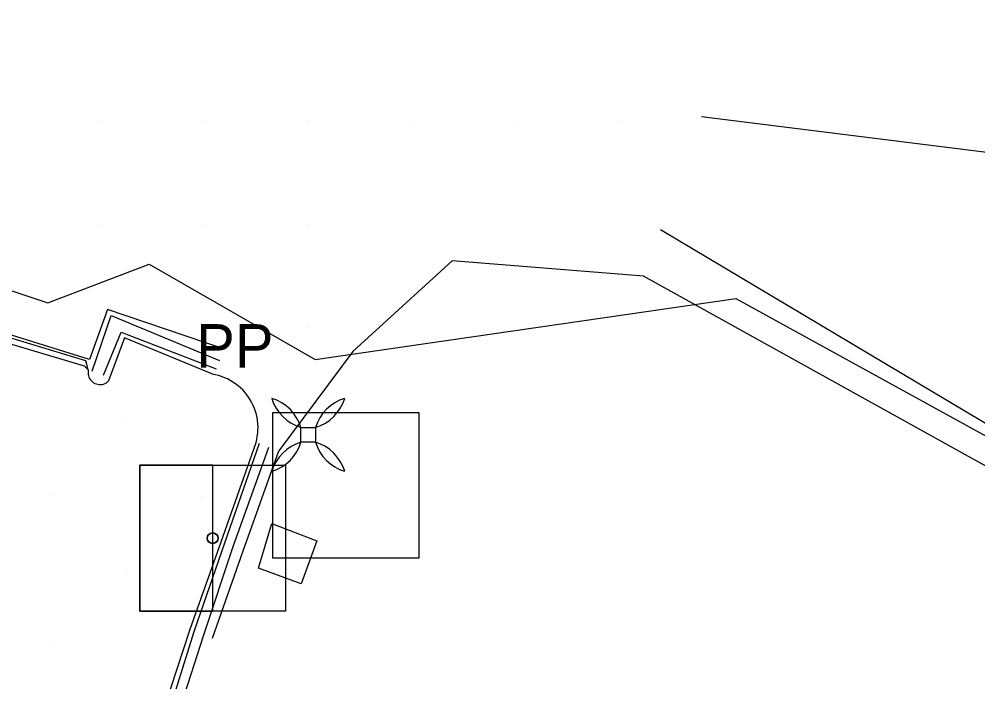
# Model space of a CAD drawing. Extents: x 1602514 to 1609837, y 863887 to 871157.
# Drawn here: x 1604009.5 to 1604147.6, y 867540.9 to 867636.3 of the extents above; entities that cross this region are included whole.
import ezdxf

# ---------------------------------------------------------------- set-up
doc = ezdxf.new("R2010")
doc.units = 0
for name, color, linetype in [('Photo-Anchor', 7, 'Continuous'), ('Survey-Buildings', 7, 'Continuous'), ('Survey-Curbs', 7, 'Continuous'), ('Survey-Edge of pavement', 7, 'Continuous'), ('Survey-Entrances', 7, 'Continuous'), ('Survey-Ridge Lines', 7, 'Continuous'), ('Survey-Spot dirt', 7, 'Continuous'), ('Survey-Vegetation trees', 7, 'Continuous'), ('Survey-Walls', 7, 'Continuous'), ('Utility-Pole', 7, 'Continuous')]:
    doc.layers.add(name, color=color, linetype=linetype)

msp = doc.modelspace()

# ---------------------------------------------------------------- linework, layer by layer
at = {"layer": 'Photo-Anchor'}
msp.add_lwpolyline([(1604050.09, 867577.53), (1604052.19, 867577.53), (1604052.19, 867575.43), (1604050.09, 867575.43)], close=True, dxfattribs=at)
msp.add_lwpolyline([(1604050.09, 867577.53), (1604052.19, 867577.53), (1604052.19, 867575.43), (1604050.09, 867575.43)], close=True, dxfattribs=at)
for centre, radius, start, end in [((1604044.09, 867575.72), 6.27, 16.7236, 73.2821), ((1604051.91, 867583.55), 6.29, 196.8106, 253.1951), ((1604044.09, 867575.72), 6.27, 16.7236, 73.2821), ((1604051.91, 867583.55), 6.29, 196.8106, 253.1951), ((1604058.19, 867575.72), 6.27, 106.7179, 163.2764), ((1604050.37, 867583.55), 6.29, 286.8049, 343.1894), ((1604058.19, 867575.72), 6.27, 106.7179, 163.2764), ((1604050.37, 867583.55), 6.29, 286.8049, 343.1894), ((1604044.09, 867577.23), 6.27, 286.7179, 343.2764), ((1604051.91, 867569.41), 6.29, 106.8049, 163.1894), ((1604044.09, 867577.23), 6.27, 286.7179, 343.2764), ((1604051.91, 867569.41), 6.29, 106.8049, 163.1894), ((1604058.19, 867577.23), 6.27, 196.7236, 253.2821), ((1604050.37, 867569.41), 6.29, 16.8106, 73.1951), ((1604058.19, 867577.23), 6.27, 196.7236, 253.2821), ((1604050.37, 867569.41), 6.29, 16.8106, 73.1951)]:
    msp.add_arc(centre, radius, start, end, dxfattribs=at)
at = {"layer": 'Survey-Buildings'}
msp.add_lwpolyline([(1604043.98, 867557.3), (1604045.89, 867563.73), (1604052.37, 867561.2), (1604050.11, 867555.03)], close=True, dxfattribs=at)
msp.add_lwpolyline([(1604043.98, 867557.3), (1604045.89, 867563.73), (1604052.37, 867561.2), (1604050.11, 867555.03)], close=True, dxfattribs=at)
at = {"layer": 'Survey-Curbs'}
for points in [[(1604019.47, 867585.84), (1604019.12, 867587.16), (1603987.37, 867596.76), (1603941.48, 867609.84), (1603941.32, 867609.45)], [(1604019.47, 867585.84), (1604019.12, 867587.16), (1603987.37, 867596.76), (1603941.48, 867609.84), (1603941.32, 867609.45)], [(1604019.47, 867585.84), (1604018.9, 867586.37), (1603987.01, 867595.85), (1603941.32, 867609.45)], [(1604019.47, 867585.84), (1604018.9, 867586.37), (1603987.01, 867595.85), (1603941.32, 867609.45)]]:
    msp.add_lwpolyline(points, dxfattribs=at)
at = {"layer": 'Survey-Edge of pavement'}
for points in [[(1604037.52, 867585.18), (1604024.7, 867590.46), (1604022.4, 867584.24)], [(1604037.52, 867585.18), (1604024.7, 867590.46), (1604022.4, 867584.24)], [(1604019.47, 867585.84), (1604019.43, 867585.63), (1604019.43, 867585.42), (1604019.44, 867585.21), (1604019.49, 867585), (1604019.56, 867584.79), (1604019.65, 867584.6), (1604019.77, 867584.42), (1604019.91, 867584.26), (1604020.07, 867584.12), (1604020.24, 867583.99), (1604020.43, 867583.89), (1604020.63, 867583.81), (1604020.83, 867583.76), (1604021.04, 867583.73), (1604021.26, 867583.73), (1604021.47, 867583.75), (1604021.68, 867583.8), (1604021.88, 867583.87), (1604022.07, 867583.97), (1604022.24, 867584.09), (1604022.4, 867584.24)], [(1604019.47, 867585.84), (1604019.43, 867585.63), (1604019.43, 867585.42), (1604019.44, 867585.21), (1604019.49, 867585), (1604019.56, 867584.79), (1604019.65, 867584.6), (1604019.77, 867584.42), (1604019.91, 867584.26), (1604020.07, 867584.12), (1604020.24, 867583.99), (1604020.43, 867583.89), (1604020.63, 867583.81), (1604020.83, 867583.76), (1604021.04, 867583.73), (1604021.26, 867583.73), (1604021.47, 867583.75), (1604021.68, 867583.8), (1604021.88, 867583.87), (1604022.07, 867583.97), (1604022.24, 867584.09), (1604022.4, 867584.24)], [(1604043.62, 867575.39), (1604043.73, 867575.83), (1604043.81, 867576.27), (1604043.87, 867576.72), (1604043.9, 867577.17), (1604043.91, 867577.63), (1604043.89, 867578.08), (1604043.84, 867578.53), (1604043.77, 867578.98), (1604043.67, 867579.42), (1604043.54, 867579.86), (1604043.4, 867580.28), (1604043.22, 867580.7), (1604043.02, 867581.11), (1604042.8, 867581.51), (1604042.56, 867581.89), (1604042.29, 867582.25), (1604042.01, 867582.61), (1604041.7, 867582.94), (1604041.38, 867583.26), (1604041.03, 867583.55), (1604040.68, 867583.83), (1604040.3, 867584.08), (1604039.91, 867584.32), (1604039.51, 867584.53), (1604039.1, 867584.71), (1604038.67, 867584.88), (1604038.24, 867585.01), (1604037.8, 867585.13), (1604037.52, 867585.18)], [(1604043.62, 867575.39), (1604043.73, 867575.83), (1604043.81, 867576.27), (1604043.87, 867576.72), (1604043.9, 867577.17), (1604043.91, 867577.63), (1604043.89, 867578.08), (1604043.84, 867578.53), (1604043.77, 867578.98), (1604043.67, 867579.42), (1604043.54, 867579.86), (1604043.4, 867580.28), (1604043.22, 867580.7), (1604043.02, 867581.11), (1604042.8, 867581.51), (1604042.56, 867581.89), (1604042.29, 867582.25), (1604042.01, 867582.61), (1604041.7, 867582.94), (1604041.38, 867583.26), (1604041.03, 867583.55), (1604040.68, 867583.83), (1604040.3, 867584.08), (1604039.91, 867584.32), (1604039.51, 867584.53), (1604039.1, 867584.71), (1604038.67, 867584.88), (1604038.24, 867585.01), (1604037.8, 867585.13), (1604037.52, 867585.18)], [(1604024.29, 867515.96), (1604024.24, 867517.26), (1604024.76, 867519.96), (1604034.14, 867548.5), (1604038.61, 867561.09), (1604043.62, 867575.39)], [(1604024.29, 867515.96), (1604024.24, 867517.26), (1604024.76, 867519.96), (1604034.14, 867548.5), (1604038.61, 867561.09), (1604043.62, 867575.39)]]:
    msp.add_lwpolyline(points, dxfattribs=at)
msp.add_circle((1604037.38, 867561.6), 0.75, dxfattribs=at)
msp.add_circle((1604037.38, 867561.6), 0.75, dxfattribs=at)
at = {"layer": 'Survey-Entrances'}
msp.add_lwpolyline([(1604248.11, 867529.03), (1604207.83, 867545), (1604150.62, 867570.9), (1604099.42, 867599.35), (1604071.88, 867601.52), (1604057.58, 867588.48), (1604046.89, 867574.19)], dxfattribs=at)
msp.add_lwpolyline([(1604248.11, 867529.03), (1604207.83, 867545), (1604150.62, 867570.9), (1604099.42, 867599.35), (1604071.88, 867601.52), (1604057.58, 867588.48), (1604046.89, 867574.19)], dxfattribs=at)
at = {"layer": 'Survey-Ridge Lines'}
for points in [[(1604256.62, 867563.35), (1604223.15, 867578.13), (1604169.61, 867614.55), (1604107.77, 867622.27)], [(1604256.62, 867563.35), (1604223.15, 867578.13), (1604169.61, 867614.55), (1604107.77, 867622.27)], [(1604039.07, 867588.82), (1604022.23, 867594.55), (1604019.64, 867587.34), (1603987.58, 867597.3), (1603942.14, 867611.46), (1603936.19, 867612.28), (1603933.42, 867605.46), (1603928.72, 867596.17), (1603921.81, 867581.4)], [(1604039.07, 867588.82), (1604022.23, 867594.55), (1604019.64, 867587.34), (1603987.58, 867597.3), (1603942.14, 867611.46), (1603936.19, 867612.28), (1603933.42, 867605.46), (1603928.72, 867596.17), (1603921.81, 867581.4)], [(1604251.39, 867542.25), (1604212.48, 867555.06), (1604152.71, 867575.7), (1604101.85, 867606.02)], [(1604251.39, 867542.25), (1604212.48, 867555.06), (1604152.71, 867575.7), (1604101.85, 867606.02)], [(1604037.34, 867547.18), (1604041.79, 867559.77), (1604046.89, 867574.19)], [(1604037.34, 867547.18), (1604041.79, 867559.77), (1604046.89, 867574.19)]]:
    msp.add_lwpolyline(points, dxfattribs=at)
msp.add_circle((1604037.38, 867561.6), 0.8, dxfattribs=at)
msp.add_circle((1604037.38, 867561.6), 0.8, dxfattribs=at)
at = {"layer": 'Survey-Spot dirt'}
for p, q in [((1604020.97, 867621.65), (1604020.97, 867621.65)), ((1604020.97, 867621.65), (1604020.97, 867621.65)), ((1604035.89, 867621.65), (1604035.89, 867621.65)), ((1604035.89, 867621.65), (1604035.89, 867621.65)), ((1604051.18, 867621.69), (1604051.18, 867621.69)), ((1604051.18, 867621.69), (1604051.18, 867621.69)), ((1604065.99, 867621.63), (1604065.99, 867621.63)), ((1604065.99, 867621.63), (1604065.99, 867621.63)), ((1604081.18, 867621.66), (1604081.18, 867621.66)), ((1604081.18, 867621.66), (1604081.18, 867621.66)), ((1604096.2, 867621.75), (1604096.2, 867621.75)), ((1604096.2, 867621.75), (1604096.2, 867621.75)), ((1604020.92, 867606.66), (1604020.92, 867606.66)), ((1604020.92, 867606.66), (1604020.92, 867606.66)), ((1604035.92, 867606.72), (1604035.92, 867606.72)), ((1604035.92, 867606.72), (1604035.92, 867606.72)), ((1604050.98, 867606.71), (1604050.98, 867606.71)), ((1604050.98, 867606.71), (1604050.98, 867606.71)), ((1604051.06, 867591.97), (1604051.06, 867591.97)), ((1604051.06, 867591.97), (1604051.06, 867591.97)), ((1604025.07, 867578.24), (1604025.07, 867578.24)), ((1604025.07, 867578.24), (1604025.07, 867578.24)), ((1604014.43, 867567.72), (1604014.43, 867567.72)), ((1604014.43, 867567.72), (1604014.43, 867567.72)), ((1604035.67, 867567.54), (1604035.67, 867567.54)), ((1604035.67, 867567.54), (1604035.67, 867567.54)), ((1604025.11, 867556.96), (1604025.11, 867556.96)), ((1604025.11, 867556.96), (1604025.11, 867556.96)), ((1604014.53, 867546.36), (1604014.53, 867546.36)), ((1604014.53, 867546.36), (1604014.53, 867546.36))]:
    msp.add_line(p, q, dxfattribs=at)
at = {"layer": 'Survey-Vegetation trees'}
msp.add_lwpolyline([(1603881.33, 867636.34), (1603931.46, 867617.09), (1603967.01, 867610.96), (1604013.65, 867595.51), (1604028.22, 867601.05), (1604052.12, 867587.34), (1604112.74, 867596.09), (1604163.16, 867568.39), (1604220.58, 867545.93), (1604254.38, 867535.73), (1604293.73, 867511.81), (1604322, 867501.61), (1604349.69, 867492.86), (1604392.82, 867459.91), (1604397.49, 867424.62)], dxfattribs=at)
msp.add_lwpolyline([(1603881.33, 867636.34), (1603931.46, 867617.09), (1603967.01, 867610.96), (1604013.65, 867595.51), (1604028.22, 867601.05), (1604052.12, 867587.34), (1604112.74, 867596.09), (1604163.16, 867568.39), (1604220.58, 867545.93), (1604254.38, 867535.73), (1604293.73, 867511.81), (1604322, 867501.61), (1604349.69, 867492.86), (1604392.82, 867459.91), (1604397.49, 867424.62)], dxfattribs=at)
at = {"layer": 'Survey-Walls'}
for points in [[(1604020.02, 867585.65), (1604022.77, 867593.66), (1604038.37, 867587.18)], [(1604020.02, 867585.65), (1604022.77, 867593.66), (1604038.37, 867587.18)], [(1604021.65, 867585.08), (1604024.21, 867591.27), (1604037.86, 867585.98)], [(1604021.65, 867585.08), (1604024.21, 867591.27), (1604037.86, 867585.98)], [(1604044.07, 867575.22), (1604039.1, 867560.89), (1604034.73, 867548.26), (1604025.77, 867519.69), (1604024.89, 867517.07), (1604026.21, 867516.69), (1604026.97, 867519.36), (1604036.1, 867547.69), (1604040.31, 867560.39), (1604045.49, 867574.7)], [(1604044.07, 867575.22), (1604039.1, 867560.89), (1604034.73, 867548.26), (1604025.77, 867519.69), (1604024.89, 867517.07), (1604026.21, 867516.69), (1604026.97, 867519.36), (1604036.1, 867547.69), (1604040.31, 867560.39), (1604045.49, 867574.7)]]:
    msp.add_lwpolyline(points, dxfattribs=at)
at = {"layer": 'Utility-Pole'}
for points in [[(1604046.06, 867579.71), (1604067.07, 867579.71), (1604067.07, 867558.7), (1604046.06, 867558.7)], [(1604046.06, 867579.71), (1604067.07, 867579.71), (1604067.07, 867558.7), (1604046.06, 867558.7)], [(1604026.88, 867551.1), (1604037.38, 867551.1), (1604037.38, 867572.11), (1604026.88, 867572.11)], [(1604026.88, 867572.11), (1604047.88, 867572.11), (1604047.88, 867551.1), (1604026.88, 867551.1)], [(1604026.88, 867551.1), (1604037.38, 867551.1), (1604037.38, 867572.11), (1604026.88, 867572.11)], [(1604026.88, 867572.11), (1604047.88, 867572.11), (1604047.88, 867551.1), (1604026.88, 867551.1)]]:
    msp.add_lwpolyline(points, close=True, dxfattribs=at)

# ---------------------------------------------------------------- texts
msp.add_text('PP', height=6.251, dxfattribs=at).set_placement((1604035, 867586.17))
msp.add_text('PP', height=6.251, dxfattribs=at).set_placement((1604035, 867586.17))

doc.saveas('drawing.dxf')
